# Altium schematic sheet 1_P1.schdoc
size 309 x 223 mm; Symbol: Sheet-Symbol_A4; Device: Sheet-Symbol_A4; @Page Name: P1; @Create Date: 2023-08-13; @Page Count: 1; @Page No: 1; @Project Name: 3rd-Chebyshev-BPF-1.8-30M; @Schematic Name: Schematic1; @Update Date: 2023-08-13; Company: 嘉立创EDA; Page Size: A4; Version: V1.0
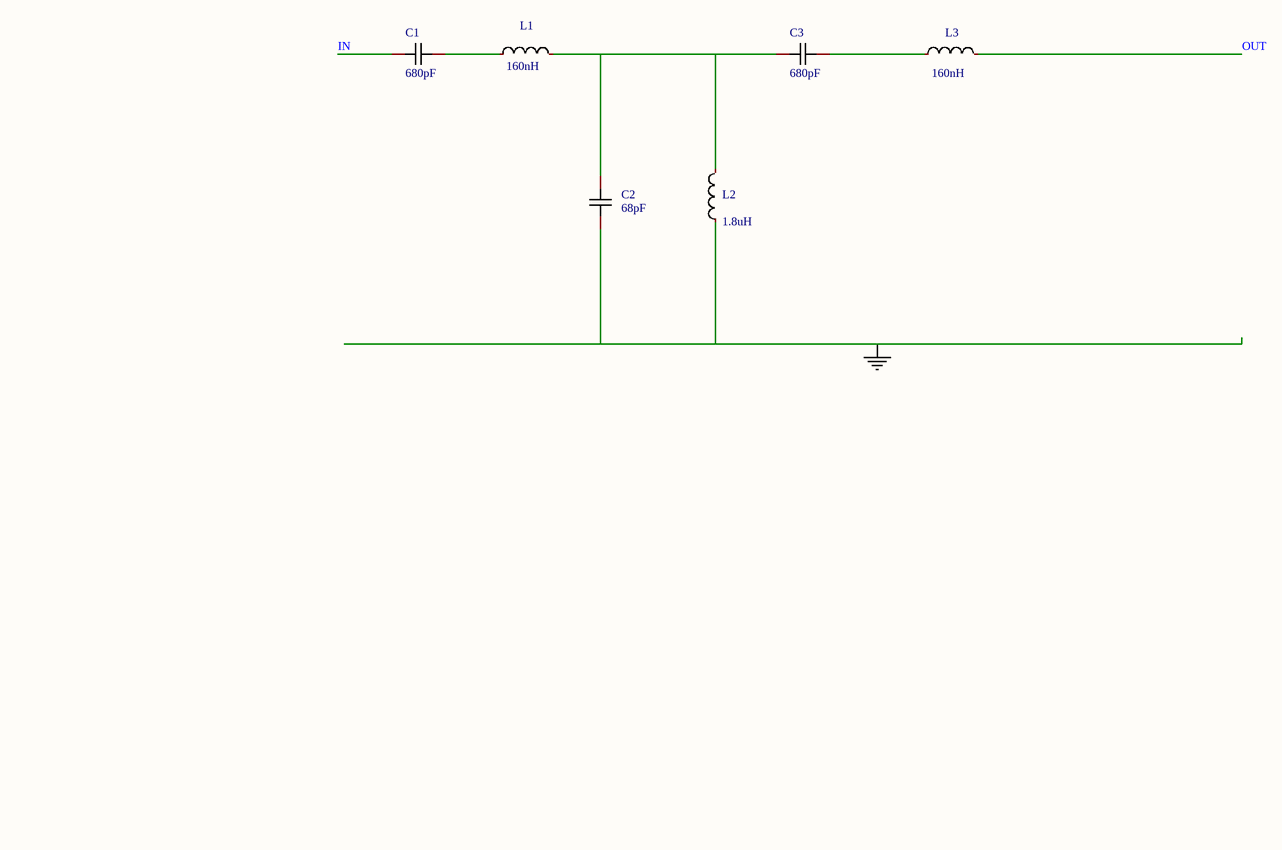
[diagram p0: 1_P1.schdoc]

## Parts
C1  680pF  [CAP-TH_L8.0-W4.0-P5.00-D1.2]
C2  68pF  [CAP-TH_L8.0-W4.0-P5.00-D1.2]
C3  680pF  [CAP-TH_L8.0-W4.0-P5.00-D1.2]
L1  Inductance: 160nH  [直插电感8mm]  (hidden comment: 直插电感8mm)
L2  Inductance: 1.8uH  [直插电感8mm]  (hidden comment: 直插电感8mm)
L3  Inductance: 160nH  [直插电感8mm]  (hidden comment: 直插电感8mm)

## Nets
NetC2_1: C2.1 L2.1
IN: C1.2
OUT: L3.2
NetC1_1: C1.1 L1.1
NetC2_2: C2.2 C3.2 L1.2 L2.2
NetC3_1: C3.1 L3.1

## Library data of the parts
C1-C3 = CT81-M7Y5P1B821KSE: 容值:820pF;精度:±10%;额定电压:2kV;温度系数:Y5P;; Manufacturer: FH(风华); Add into BOM: yes; Tolerance: ±10%; Voltage Rated: 2kV; Temperature Coefficient: Y5P; φD: 8mm; Body Thickness: 4mm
